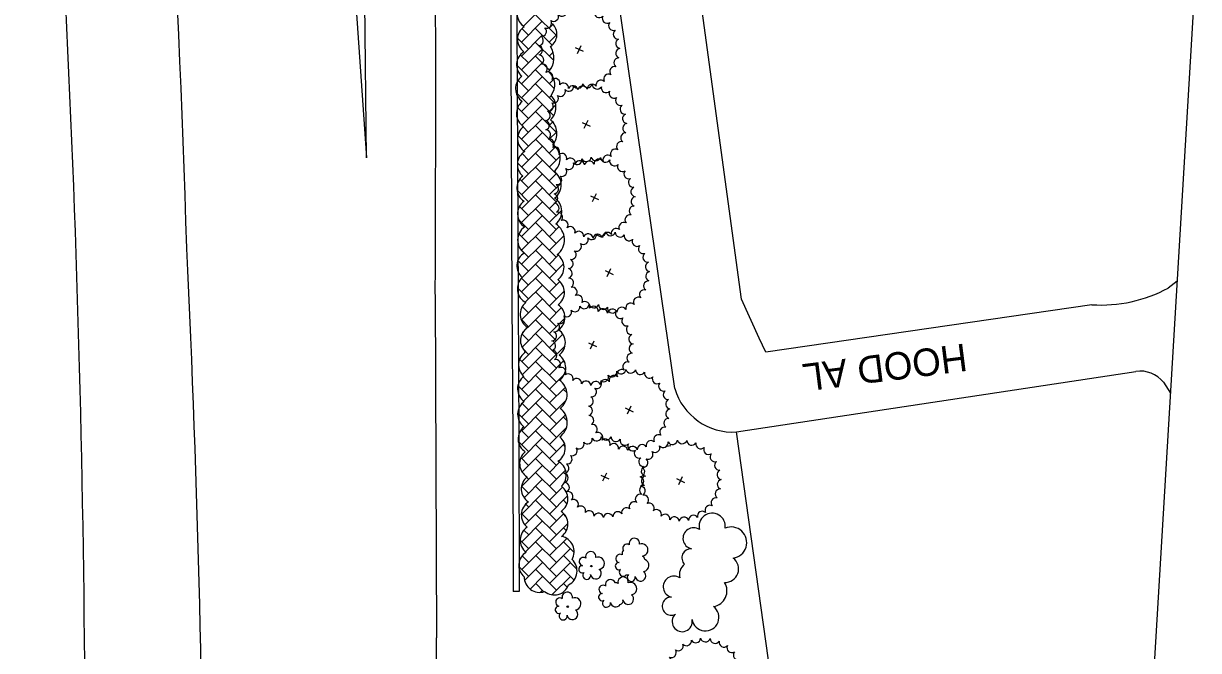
# Model space of a CAD drawing. Extents: x -9648 to 41057, y -12373 to 40276.
# Drawn here: x 9246.2 to 9485.7, y -2212.4 to -2084.6 of the extents above; entities that cross this region are included whole.
import ezdxf

# ---------------------------------------------------------------- set-up
doc = ezdxf.new("R2010")
doc.units = 0
for name, color, linetype in [('Default', 7, 'Continuous'), ('SC_Scratch1', 7, 'Continuous'), ('SH_Data', 7, 'Continuous')]:
    doc.layers.add(name, color=color, linetype=linetype)

# ---------------------------------------------------------------- blocks, each defined once
blk = doc.blocks.new('15_PIN')
at = {"layer": 'Default'}
for p, q in [((-2.75, 0), (2.75, 0)), ((0, 2.75), (0, -2.75))]:
    blk.add_line(p, q, dxfattribs=at)
for centre, start, end in [((-11.63, 23.15), 222.65669, 10.67665), ((-5.97, 25.21), 209.32335, 357.34332), ((0, 25.91), 195.99002, 344.00998), ((5.97, 25.21), 182.65669, 330.67665), ((11.63, 23.15), 169.32335, 317.34332), ((-20.78, 15.47), 249.32335, 37.34332), ((-16.65, 19.85), 235.99002, 24.00998), ((16.65, 19.85), 155.99002, 304.00998), ((20.78, 15.47), 142.65669, 290.67665), ((-23.79, 10.26), 262.65669, 50.67665), ((23.79, 10.26), 129.32335, 277.34332), ((-25.51, 4.5), 275.99002, 64.00998), ((-25.86, -1.51), 289.32335, 77.34332), ((25.51, 4.5), 115.99002, 264.00998), ((25.86, -1.51), 102.65669, 250.67665), ((-24.82, -7.43), 302.65669, 90.67665), ((24.82, -7.43), 89.32335, 237.34332), ((-22.44, -12.95), 315.99002, 104.00998), ((22.44, -12.95), 75.99002, 224.00998), ((-18.84, -17.78), 329.32335, 117.34332), ((-14.24, -21.65), 342.65669, 130.67665), ((-8.86, -24.35), 355.99002, 144.00998), ((8.86, -24.35), 35.99002, 184.00998), ((14.24, -21.65), 49.32335, 197.34332), ((18.84, -17.78), 62.65669, 210.67665), ((-3.01, -25.73), 9.32335, 157.34332), ((3.01, -25.73), 22.65669, 170.67665)]:
    blk.add_arc(centre, 3.05, start, end, dxfattribs=at)

msp = doc.modelspace()

# ---------------------------------------------------------------- linework, layer by layer
at = {"layer": 'SC_Scratch1'}
msp.add_line((9378.16, -2170.67), (9377.21, -2170.8), dxfattribs=at)
at = {"layer": 'SH_Data'}
for p, q in [((9378.96, -2158.98), (9349.64, -1956.4)), ((9348.14, -2085.17), (9351.97, -2081.34)), ((9354.8, -2086.99), (9350.55, -2082.75)), ((9347.73, -2088.41), (9351.97, -2084.17)), ((9354, -2089.02), (9350.55, -2085.58)), ((9353.38, -2085.58), (9354.19, -2084.77)), ((9349.14, -2089.83), (9346.92, -2087.61)), ((9347.73, -2091.24), (9351.97, -2087)), ((9349.14, -2087), (9347.8, -2085.66)), ((9353.38, -2088.41), (9354.96, -2086.83)), ((9347.73, -2094.07), (9351.97, -2089.82)), ((9354.3, -2092.16), (9350.55, -2088.41)), ((9353.39, -2091.24), (9354.18, -2090.44)), ((9349.14, -2092.65), (9347.48, -2090.99)), ((9347.73, -2096.9), (9351.97, -2092.65)), ((9353.5, -2094.18), (9350.56, -2091.24)), ((9349.15, -2095.48), (9346.7, -2093.04)), ((9354.43, -2097.93), (9350.56, -2094.07)), ((9353.39, -2094.07), (9353.86, -2093.59)), ((9349.15, -2098.31), (9347.03, -2096.2)), ((9347.73, -2099.73), (9351.97, -2095.48)), ((9354.7, -2101.03), (9350.56, -2096.9)), ((9353.39, -2096.9), (9354.34, -2095.94)), ((9349.15, -2101.14), (9346.6, -2098.59)), ((9347.74, -2102.55), (9351.97, -2098.31)), ((9354.29, -2103.45), (9350.56, -2099.72)), ((9353.39, -2099.72), (9353.82, -2099.29)), ((9349.15, -2103.97), (9346.94, -2101.76)), ((9347.78, -2105.34), (9351.98, -2101.14)), ((9353.39, -2102.55), (9354.73, -2101.21)), ((9370.82, -2102.13), (9370.82, -2102.13)), ((9347.74, -2108.21), (9351.98, -2103.97)), ((9354.81, -2106.79), (9350.56, -2102.55)), ((9353.39, -2105.38), (9354.1, -2104.67)), ((9349.15, -2106.8), (9348.04, -2105.69)), ((9348.2, -2110.58), (9351.98, -2106.8)), ((9354.28, -2109.09), (9350.57, -2105.38)), ((9353.39, -2108.21), (9354.94, -2106.66)), ((9349.15, -2109.62), (9347, -2107.47)), ((9354.81, -2112.45), (9350.57, -2108.21)), ((9347.74, -2113.87), (9351.98, -2109.62)), ((9349.15, -2112.45), (9347.84, -2111.14)), ((9354.81, -2115.28), (9350.57, -2111.04)), ((9353.4, -2111.04), (9354.66, -2109.77)), ((9353.4, -2113.87), (9355.61, -2111.65)), ((9349.16, -2115.28), (9346.91, -2113.04)), ((9347.74, -2116.7), (9351.98, -2112.45)), ((9354.82, -2118.11), (9350.57, -2113.87)), ((9349.16, -2118.11), (9347.38, -2116.34)), ((9347.74, -2119.52), (9351.99, -2115.28)), ((9354.82, -2120.94), (9350.57, -2116.7)), ((9353.4, -2116.69), (9354.89, -2115.2)), ((9349.16, -2120.94), (9346.82, -2118.6)), ((9347.75, -2122.35), (9351.99, -2118.11)), ((9353.4, -2119.52), (9355.8, -2117.12)), ((9347.75, -2125.18), (9351.99, -2120.94)), ((9354.82, -2123.76), (9350.57, -2119.52)), ((9353.4, -2122.35), (9355.06, -2120.69)), ((9349.16, -2123.77), (9347.3, -2121.91)), ((9347.75, -2128.01), (9351.99, -2123.77)), ((9354.82, -2126.59), (9350.57, -2122.35)), ((9353.4, -2125.18), (9355.95, -2122.63)), ((9349.16, -2126.6), (9347.13, -2124.57)), ((9354.82, -2129.42), (9350.57, -2125.18)), ((9353.41, -2128.01), (9355.4, -2126.01)), ((9349.17, -2129.42), (9347.21, -2127.47)), ((9347.75, -2130.84), (9351.99, -2126.59)), ((9354.82, -2132.25), (9350.58, -2128.01)), ((9353.41, -2130.84), (9356.4, -2127.84)), ((9356.47, -2128.24), (9356.23, -2128)), ((9349.17, -2132.25), (9347.5, -2130.59)), ((9347.75, -2133.67), (9351.99, -2129.42)), ((9354.82, -2135.08), (9350.58, -2130.84)), ((9349.17, -2135.08), (9346.99, -2132.9)), ((9347.88, -2136.37), (9351.99, -2132.25)), ((9353.41, -2133.67), (9355.22, -2131.85)), ((9347.75, -2139.32), (9352, -2135.08)), ((9354.82, -2137.9), (9350.58, -2133.67)), ((9353.41, -2136.49), (9356.32, -2133.58)), ((9356.36, -2133.78), (9356.24, -2133.66)), ((9349.17, -2137.91), (9347.76, -2136.5)), ((9348.5, -2141.41), (9352, -2137.91)), ((9354.83, -2140.73), (9350.58, -2136.49)), ((9353.41, -2139.32), (9355.55, -2137.18)), ((9481.35, -2137.12), (9479.54, -2138.52)), ((9330.15, -2139.81), (9330.38, -2209.81)), ((9349.17, -2140.74), (9346.9, -2138.47)), ((9354.83, -2143.56), (9350.58, -2139.32)), ((9353.42, -2142.15), (9356.47, -2139.09)), ((9356.48, -2139.56), (9356.24, -2139.32)), ((9347.76, -2144.98), (9352, -2140.74)), ((9349.17, -2143.57), (9347.9, -2142.3)), ((9354.83, -2146.39), (9350.59, -2142.15)), ((9353.42, -2144.98), (9355.85, -2142.54)), ((9349.17, -2146.4), (9347.64, -2144.86)), ((9349.01, -2146.56), (9352, -2143.57)), ((9354.83, -2149.22), (9350.59, -2144.98)), ((9353.42, -2147.8), (9356.58, -2144.64)), ((9356.5, -2145.23), (9356.24, -2144.98)), ((9349.17, -2149.22), (9347.82, -2147.87)), ((9347.84, -2150.56), (9352, -2146.39)), ((9347.96, -2147.61), (9348.97, -2146.6)), ((9354.83, -2152.05), (9350.59, -2147.81)), ((9353.42, -2150.63), (9356.14, -2147.91)), ((9347.77, -2153.47), (9352, -2149.22)), ((9353.42, -2153.46), (9356.6, -2150.28)), ((9347.87, -2156.19), (9352, -2152.05)), ((9349.18, -2152.05), (9348.05, -2150.93)), ((9354.84, -2154.88), (9350.59, -2150.64)), ((9356.44, -2150.82), (9356.25, -2150.63)), ((9349.18, -2154.88), (9347.34, -2153.04)), ((9347.77, -2159.12), (9352.01, -2154.88)), ((9354.84, -2157.7), (9350.59, -2153.47)), ((9353.42, -2156.29), (9356.39, -2153.32)), ((9356.61, -2153.82), (9356.25, -2153.46)), ((9349.18, -2157.71), (9348.1, -2156.63)), ((9354.84, -2160.53), (9350.59, -2156.29)), ((9353.42, -2159.12), (9356.48, -2156.06)), ((9356.32, -2156.36), (9356.25, -2156.29)), ((9391.58, -2167.85), (9472.96, -2155.53)), ((9349.18, -2160.54), (9347.01, -2158.37)), ((9348.17, -2161.55), (9352.01, -2157.7)), ((9354.84, -2163.36), (9350.6, -2159.12)), ((9353.42, -2161.95), (9356.68, -2158.7)), ((9357.01, -2159.87), (9356.25, -2159.12)), ((9478.56, -2157.72), (9479.96, -2159.92)), ((9347.77, -2164.78), (9352.01, -2160.53)), ((9349.18, -2163.37), (9347.85, -2162.04)), ((9354.84, -2166.19), (9350.6, -2161.95)), ((9353.43, -2164.78), (9356.84, -2161.36)), ((9356.45, -2162.15), (9356.25, -2161.95)), ((9349.18, -2166.19), (9346.95, -2163.97)), ((9347.77, -2167.61), (9352.01, -2163.36)), ((9353.43, -2167.6), (9356.69, -2164.34)), ((9347.77, -2170.44), (9352.01, -2166.19)), ((9354.84, -2169.02), (9350.6, -2164.78)), ((9353.43, -2170.43), (9356.92, -2166.94)), ((9357.05, -2165.57), (9356.25, -2164.77)), ((9349.19, -2169.02), (9347.61, -2167.45)), ((9347.77, -2173.27), (9352.02, -2169.02)), ((9354.85, -2171.85), (9350.6, -2167.61)), ((9356.5, -2167.85), (9356.26, -2167.6)), ((9415.45, -2338.73), (9391.58, -2167.85)), ((9349.19, -2171.85), (9347.07, -2169.73)), ((9347.86, -2176.01), (9352.02, -2171.85)), ((9354.85, -2174.67), (9350.6, -2170.43)), ((9353.43, -2173.26), (9356.49, -2170.2)), ((9356.63, -2170.8), (9356.26, -2170.43)), ((9349.19, -2174.68), (9347.6, -2173.09)), ((9354.85, -2177.5), (9350.6, -2173.26)), ((9353.43, -2176.09), (9355.5, -2174.02)), ((9347.78, -2178.92), (9352.02, -2174.68)), ((9354.85, -2180.33), (9350.6, -2176.09)), ((9353.43, -2178.92), (9356.71, -2175.64)), ((9356.87, -2176.69), (9356.26, -2176.09)), ((9349.19, -2180.34), (9347.74, -2178.89)), ((9348.26, -2181.27), (9352.02, -2177.5)), ((9349.19, -2177.51), (9348.78, -2177.1)), ((9354.85, -2183.16), (9350.6, -2178.92)), ((9347.78, -2184.58), (9352.02, -2180.33)), ((9353.44, -2181.75), (9356.1, -2179.08)), ((9353.44, -2184.58), (9357.12, -2180.88)), ((9348.42, -2186.77), (9352.02, -2183.16)), ((9349.2, -2183.16), (9348.59, -2182.56)), ((9354.85, -2185.99), (9350.61, -2181.75)), ((9357, -2182.48), (9356.27, -2181.75)), ((9349.2, -2185.99), (9347.7, -2184.5)), ((9347.78, -2190.24), (9352.02, -2185.99)), ((9354.85, -2188.82), (9350.61, -2184.58)), ((9353.44, -2187.4), (9356.35, -2184.5)), ((9356.77, -2185.08), (9356.27, -2184.57)), ((9349.2, -2188.82), (9348.23, -2187.85)), ((9354.85, -2191.65), (9350.61, -2187.4)), ((9353.44, -2190.23), (9357.18, -2186.49)), ((9356.87, -2188), (9356.27, -2187.4)), ((9349.2, -2191.65), (9347.46, -2189.91)), ((9348.56, -2192.29), (9352.03, -2188.82)), ((9354.86, -2194.47), (9350.61, -2190.23)), ((9353.44, -2193.06), (9356.95, -2189.55)), ((9358.47, -2192.43), (9356.27, -2190.23)), ((9347.79, -2195.89), (9352.03, -2191.65)), ((9349.2, -2194.48), (9347.84, -2193.12)), ((9354.86, -2197.3), (9350.62, -2193.06)), ((9353.44, -2195.89), (9357.68, -2191.65)), ((9359.04, -2195.83), (9356.27, -2193.06)), ((9349.2, -2197.3), (9347.19, -2195.3)), ((9348.37, -2198.14), (9352.03, -2194.48)), ((9353.45, -2198.72), (9357.69, -2194.47)), ((9349.47, -2199.87), (9352.03, -2197.3)), ((9354.86, -2200.13), (9350.62, -2195.89)), ((9353.94, -2201.05), (9357.69, -2197.3)), ((9358.45, -2198.06), (9356.27, -2195.89)), ((9347.28, -2200.4), (9346.04, -2200.4)), ((9352.31, -2200.41), (9350.62, -2198.72)), ((9351.63, -2200.54), (9352.03, -2200.13)), ((9357.09, -2199.54), (9356.27, -2198.72))]:
    msp.add_line(p, q, dxfattribs=at)
for points in [[(9344.86, -1879.89), (9345.14, -1915.94), (9345, -1937.2), (9345.1, -1959.92), (9345.34, -2040.63), (9345.78, -2141.31), (9345.98, -2168.75), (9346.04, -2200.4)], [(9346.11, -1879.88), (9346.39, -1915.94), (9346.25, -1937.2), (9346.35, -1959.92), (9346.59, -2040.63), (9347.03, -2141.3), (9347.22, -2168.74), (9347.28, -2200.4)], [(9492.44, -1956.32), (9485.7, -2063.92), (9471.83, -2295.93), (9465.1, -2407.93)], [(9313.31, -2070.82), (9316.13, -2112.01), (9315.49, -2048.62), (9314.21, -1956.42)], [(9463.95, -2141.93), (9397.55, -2151.57), (9396.15, -2148.77), (9392.55, -2140.77), (9367.44, -1956.39)]]:
    msp.add_lwpolyline(points, dxfattribs=at)
for centre in [(9361.97, -2195.2), (9357.16, -2203.48)]:
    msp.add_circle(centre, 0.155, dxfattribs=at)
for centre, radius, start, end in [((6046.56, -2240.52), 3212.26, 359.80118, 5.07318), ((5849.08, -2238.3), 3432.15, 1.80118, 4.71018), ((732.98, -2098.86), 8597.27, 359.727183, 0.949183), ((9349.95, -2082.62), 3.12, 127.7843, 237.7843), ((9350.04, -2087.85), 3.13, 124.2093, 234.2093), ((9351.92, -2086.8), 3.04, 305.1024, 46.0014), ((9349.76, -2093.02), 3.05, 120.4347, 230.4347), ((9349.98, -2091.61), 4.36, 320.181, 32.169), ((9350.94, -2097.08), 3.58, 322.4721, 48.2996), ((9349.65, -2097.9), 3.13, 125.995, 235.995), ((9351.25, -2101.69), 3.51, 313.2784, 43.7759), ((9349.81, -2102.96), 3.12, 127.7843, 237.7843), ((9351.38, -2107), 3.58, 319.4237, 50.4041), ((9350.06, -2108.08), 3.12, 127.7843, 237.7843), ((9352.32, -2112.13), 3.32, 307.7843, 57.7843), ((9349.94, -2113.35), 3.05, 120.4347, 230.4347), ((9349.91, -2118.17), 3.12, 127.7843, 237.7843), ((9352.51, -2117.51), 3.32, 306.1002, 56.1002), ((9350.15, -2123.43), 3.22, 126.0492, 236.0492), ((9352.74, -2122.92), 3.22, 307.7843, 57.7843), ((9350.17, -2128.77), 3.23, 124.3174, 234.3174), ((9352.69, -2128.69), 3.81, 307.7843, 57.7843), ((5885.87, -2289.14), 3397.38, 357.78218, 2.67718), ((9349.83, -2134.02), 3.05, 120.4347, 230.4347), ((9353.27, -2134.29), 3.13, 305.9951, 55.9951), ((9350.03, -2138.66), 3.14, 133.1381, 243.1381), ((9353.36, -2139.41), 3.13, 305.995, 55.995), ((9465.77, -2112.89), 29.1, 266.4062, 298.2482), ((9350.6, -2143.87), 3.13, 129.5735, 239.5735), ((9353.45, -2144.53), 3.13, 305.995, 55.995), ((9350.57, -2149.2), 3.05, 120.4347, 230.4347), ((9353.54, -2149.65), 3.13, 305.995, 55.995), ((9350.17, -2154.18), 3.05, 120.4347, 230.4347), ((9353.63, -2154.78), 3.13, 305.9951, 55.9951), ((9350.06, -2159.07), 3.13, 125.995, 235.995), ((9353.51, -2160.23), 3.52, 306.1937, 56.1937), ((9473.83, -2161.53), 6.07, 38.8592, 98.3102), ((9390.84, -2155.5), 12.38, 196.3452, 273.4327), ((9350.07, -2164.25), 3.13, 124.2093, 234.2093), ((9353.55, -2165.93), 3.52, 304.6056, 54.6056), ((9350.16, -2169.25), 3.12, 127.7843, 237.7843), ((9353.6, -2171.19), 3.05, 300.4347, 50.4347), ((9350.48, -2174.31), 3.13, 129.5735, 239.5735), ((9353.73, -2176.62), 3.14, 313.1381, 63.1381), ((9350.81, -2179.47), 3.12, 127.7843, 237.7843), ((9354.05, -2181.45), 3.13, 304.2093, 54.2093), ((9350.83, -2184.77), 3.14, 122.4305, 232.4305), ((9354.06, -2186.63), 3.13, 305.995, 55.995), ((9386.59, -2187.08), 2.67, 351.9296, 194.2439), ((9350.6, -2189.9), 3.14, 122.4305, 232.4305), ((9382.81, -2189.54), 2.17, 56.6142, 257.8219), ((9390.45, -2190.4), 3.19, 277.7319, 112.2414), ((9355.32, -2192.26), 3.15, 329.5782, 79.5782), ((9369.23, -2191.56), 0.859, 56.6142, 210.1093), ((9370.73, -2190.58), 1.06, 351.9296, 194.2439), ((9372.25, -2191.9), 1.26, 277.7319, 112.2414), ((9350.23, -2195.02), 3.05, 120.4347, 230.4347), ((9360.36, -2194.27), 0.859, 56.6142, 257.8219), ((9361.86, -2193.29), 1.06, 351.9296, 194.2439), ((9363.38, -2194.61), 1.26, 277.7319, 112.2414), ((9367.8, -2193.65), 0.859, 56.6142, 257.8219), ((9369.29, -2192.67), 1.06, 140.0631, 194.2439), ((9371.77, -2194.03), 1.09, 10.0024, 53.358), ((9382.25, -2193.5), 1.84, 86.789, 225.6128), ((9355.88, -2196.19), 3.18, 297.1686, 47.1686), ((9360.13, -2195.83), 0.728, 86.789, 298.7584), ((9367.57, -2195.21), 0.728, 86.789, 298.7584), ((9372.46, -2195.04), 1.26, 277.7319, 72.1402), ((9382.57, -2196.95), 2.67, 126.9671, 194.2439), ((9389.23, -2195.77), 2.76, 267.0431, 53.358), ((9351.41, -2197.42), 3.13, 179.1139, 289.1139), ((9361.03, -2197.08), 0.813, 131.8468, 12.3255), ((9362.9, -2196.73), 1.09, 188.9565, 53.358), ((9365.88, -2198.99), 1.06, 21.5624, 194.2439), ((9368.45, -2198.47), 1.06, 351.9296, 194.2439), ((9368.47, -2196.46), 0.813, 131.8468, 319.7794), ((9369.21, -2196.27), 0.728, 260.3508, 298.7584), ((9370.1, -2197.51), 0.813, 131.8468, 12.3255), ((9371.98, -2197.17), 1.09, 188.9565, 53.358), ((9378.79, -2199.41), 2.17, 56.6142, 257.8219), ((9354.41, -2197.98), 3.1, 230.5133, 340.5133), ((9357.05, -2201.57), 1.06, 351.9296, 194.2439), ((9364.38, -2199.96), 0.859, 56.6142, 257.8219), ((9366.95, -2199.45), 0.859, 56.6142, 95.3894), ((9369.97, -2199.79), 1.26, 277.7319, 112.2414), ((9386.42, -2200.27), 3.19, 277.7319, 33.2932), ((9355.55, -2202.55), 0.859, 56.6142, 257.8219), ((9358.58, -2202.89), 1.26, 277.7319, 112.2414), ((9364.16, -2201.53), 0.728, 86.789, 298.7584), ((9365.05, -2202.77), 0.813, 131.8468, 12.3255), ((9366.93, -2202.43), 1.09, 188.9565, 325.5139), ((9367.62, -2202.26), 0.813, 284.8296, 12.3255), ((9369.49, -2201.92), 1.09, 188.9565, 53.358), ((9378.23, -2203.37), 1.84, 86.789, 298.7584), ((9355.33, -2204.11), 0.728, 86.789, 298.7584), ((9356.22, -2205.36), 0.813, 131.8468, 12.3255), ((9358.1, -2205.01), 1.09, 188.9565, 53.358), ((9380.48, -2206.51), 2.05, 131.8468, 12.3255), ((9385.21, -2205.64), 2.76, 188.9565, 53.358), ((5351.48, -2263.5), 3979.27, 357.83218, 0.77318)]:
    msp.add_arc(centre, radius, start, end, dxfattribs=at)

# ---------------------------------------------------------------- block references
at = {"layer": 'SH_Data', "xscale": 0.32808397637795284, "yscale": 0.32808397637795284, "rotation": 64.61472397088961}
for p in [(9359.5, -2089.88), (9360.9, -2105.16), (9362.61, -2120.09), (9365.57, -2135.35), (9362.18, -2150.08), (9369.69, -2163.35), (9364.72, -2177.02), (9380.16, -2177.75), (9384.91, -2218.15)]:
    msp.add_blockref('15_PIN', p, dxfattribs=at)

# ---------------------------------------------------------------- texts
at = {"layer": 'SC_Scratch1'}
msp.add_text('HOOD AL', height=5.6, rotation=187.2732, dxfattribs=at).set_placement((9438.14, -2149.81))

doc.saveas('drawing.dxf')
